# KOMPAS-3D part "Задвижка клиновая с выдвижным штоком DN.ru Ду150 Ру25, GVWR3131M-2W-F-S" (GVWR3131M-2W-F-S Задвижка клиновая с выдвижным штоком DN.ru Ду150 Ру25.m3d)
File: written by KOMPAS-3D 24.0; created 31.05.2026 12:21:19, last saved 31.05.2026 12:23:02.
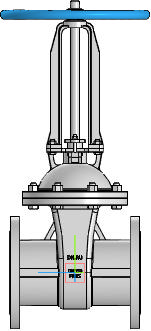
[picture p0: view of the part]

Document properties: Автор: R2D2; Полное имя файла: E:\Работа\Зайцев\GVWR3131M-2W-F-S Задвижка клиновая 30нж64нж DN.ru  Ду50-150 Ру25\исходные данные\DN150\dn150\GVWR3131M-2W-F-S Задвижка клиновая с выдвижным штоком DN.ru Ду150 Ру25.m3d

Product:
- Part/product: Задвижка клиновая с выдвижным штоком DN.ru Ду150 Ру25  | designation GVWR3131M-2W-F-S
    Масса: 61
    Раздел спецификации: Прочие изделия
    Примечание: D040-07877

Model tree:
1. Операция без истории:1

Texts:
  GVWR3131M-2W-F-S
